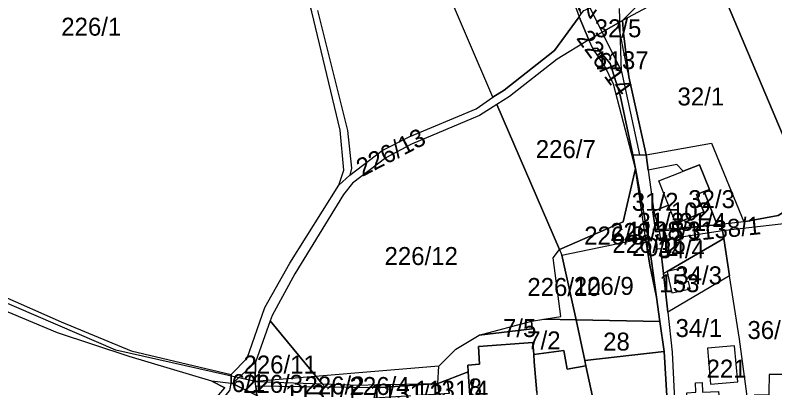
# Model space of a CAD drawing. Extents: x -623250 to -619626, y -1079612 to -1075424.
# Drawn here: x -622012.8 to -621589.3, y -1077337.8 to -1077130.2 of the extents above; entities that cross this region are included whole.
import ezdxf

# ---------------------------------------------------------------- set-up
doc = ezdxf.new("R2010")
doc.units = 0
for name, color, linetype in [('Cestní síť', 7, 'Continuous'), ('Hranice převzatá (k_ú_Džbánov - vnitřní obvod)', 7, 'Continuous'), ('Hranice šetřená (k_ú_Džbánov - vnitřní obvod)', 7, 'Continuous'), ('Parcela nároku', 7, 'Continuous'), ('Parcelní číslo', 7, 'Continuous')]:
    doc.layers.add(name, color=color, linetype=linetype)

msp = doc.modelspace()

# ---------------------------------------------------------------- linework, layer by layer
at = {"layer": 'Cestní síť'}
for p, q in [((-621700.59, -1077109.27), (-621674.74, -1077161.53)), ((-621674.74, -1077161.53), (-621675.8, -1077126.45)), ((-621674.74, -1077161.53), (-621664.7, -1077208.02)), ((-621956.73, -1077316.77), (-622052.88, -1077275.46)), ((-621878.96, -1077334.38), (-621956.73, -1077316.77)), ((-621776.53, -1077325.85), (-621878.96, -1077334.38))]:
    msp.add_line(p, q, dxfattribs=at)
at = {"layer": 'Hranice převzatá (k_ú_Džbánov - vnitřní obvod)'}
msp.add_lwpolyline([(-621820.79, -1077336.29), (-621811.3, -1077336.07), (-621804.95, -1077335.91), (-621777.05, -1077335.46)], dxfattribs=at)
at = {"layer": 'Hranice šetřená (k_ú_Džbánov - vnitřní obvod)'}
for points in [[(-621777.05, -1077335.46), (-621776.53, -1077325.85), (-621767.08, -1077316.28), (-621754.15, -1077308.49), (-621724.62, -1077305.04), (-621725.01, -1077300.64), (-621718.03, -1077299.58), (-621700.04, -1077299.94), (-621707.97, -1077263.85), (-621661.46, -1077254.24), (-621666.99, -1077215.55), (-621668.35, -1077208.09), (-621661.04, -1077207.94), (-621670.74, -1077164.6), (-621673.7, -1077140.26), (-621674.17, -1077133.23), (-621658.06, -1077117.09)], [(-621979.33, -1077434.11), (-621981.48, -1077418.71), (-621967.44, -1077419.71), (-621940.51, -1077416.47), (-621930.63, -1077410.65), (-621923.08, -1077402.05), (-621922.91, -1077399.82), (-621921.11, -1077391), (-621919.24, -1077381.82), (-621913.99, -1077368.92), (-621903.63, -1077352.03), (-621893.06, -1077339.39), (-621892.26, -1077335.34), (-621891.68, -1077335.41), (-621878.09, -1077342.07), (-621878.67, -1077336.93), (-621878.96, -1077334.38), (-621841.71, -1077335.6), (-621820.79, -1077336.29)]]:
    msp.add_lwpolyline(points, dxfattribs=at)
at = {"layer": 'Parcela nároku'}
for points in [[(-621862.28, -1077073.68), (-621884.15, -1076991.03), (-621993.08, -1077002.63), (-622102.16, -1077014.18), (-622094.75, -1077078.52), (-622077.89, -1077147.06), (-622076.74, -1077150.89), (-622049.49, -1077211.69), (-622030.93, -1077247.2), (-622020.83, -1077286.22), (-621987.11, -1077301.08), (-621948.12, -1077317.22), (-621892.3, -1077330.5), (-621883.37, -1077321.39), (-621873.67, -1077293.17), (-621859.64, -1077268.41), (-621832.26, -1077224.99), (-621829.56, -1077216.51), (-621831.64, -1077194.31), (-621847.29, -1077128.33)], [(-621742.89, -1077027.94), (-621730.03, -1077051.19), (-621717.08, -1077079.76), (-621698.44, -1077131.08), (-621712.03, -1077149.92), (-621740.17, -1077171.93), (-621746.44, -1077175.87), (-621802.34, -1077045.59)], [(-621737.82, -1077026.43), (-621742.89, -1077027.94), (-621730.03, -1077051.19), (-621717.08, -1077079.76), (-621698.44, -1077131.08), (-621697.15, -1077129.38), (-621704.43, -1077111.1), (-621716.26, -1077072.94), (-621722.92, -1077054.35), (-621730.97, -1077036.31)], [(-621523.17, -1077195.12), (-621571.7, -1077066.1), (-621579.59, -1077070.93), (-621623.27, -1077105.92), (-621571.51, -1077228.57), (-621549.32, -1077220.52), (-621537.72, -1077208.73)], [(-621570.38, -1077230.98), (-621571.51, -1077228.57), (-621623.27, -1077105.92), (-621674.17, -1077133.23), (-621673.7, -1077140.26), (-621670.74, -1077164.6), (-621661.04, -1077207.94), (-621624.64, -1077201.52), (-621606.64, -1077245.37), (-621587.33, -1077241.87)], [(-621892.3, -1077330.5), (-621883.37, -1077321.39), (-621873.67, -1077293.17), (-621859.64, -1077268.41), (-621832.26, -1077224.99), (-621826.2, -1077219.39), (-621808.22, -1077205.68), (-621793.14, -1077198.02), (-621755.81, -1077182.33), (-621746.44, -1077175.87), (-621740.17, -1077171.93), (-621712.03, -1077149.92), (-621698.44, -1077131.08), (-621692.89, -1077143.94), (-621710.61, -1077154.71), (-621737.17, -1077175.56), (-621744.25, -1077179.97), (-621753.86, -1077186.11), (-621791.79, -1077202.14), (-621806.2, -1077209.69), (-621824.78, -1077223.79), (-621829.76, -1077230.05), (-621856.84, -1077274.4), (-621869.44, -1077297.51), (-621870.52, -1077300.51), (-621878.78, -1077323.55), (-621891.68, -1077335.41), (-621892.26, -1077335.34)], [(-621674.17, -1077133.23), (-621676.84, -1077134.66), (-621671.56, -1077160.93), (-621670.74, -1077164.6), (-621673.7, -1077140.26)], [(-621710.61, -1077154.71), (-621737.17, -1077175.56), (-621744.25, -1077179.97), (-621709.31, -1077260.78), (-621673.9, -1077245.39), (-621666.99, -1077215.55), (-621679.28, -1077168.63), (-621684, -1077158.71), (-621690.78, -1077148.84), (-621692.89, -1077143.94)], [(-621688.26, -1077148.59), (-621681.03, -1077157.16), (-621675.57, -1077174.81), (-621668.35, -1077208.09), (-621666.99, -1077215.55), (-621679.28, -1077168.63), (-621684, -1077158.71), (-621690.78, -1077148.84)], [(-621824.78, -1077223.79), (-621829.76, -1077230.05), (-621856.84, -1077274.4), (-621869.44, -1077297.51), (-621870.52, -1077300.51), (-621841.71, -1077335.6), (-621820.79, -1077336.29), (-621811.3, -1077336.07), (-621804.95, -1077335.91), (-621777.05, -1077335.46), (-621776.53, -1077325.85), (-621767.08, -1077316.28), (-621754.15, -1077308.49), (-621725.01, -1077300.64), (-621718.03, -1077299.58), (-621708.56, -1077298.04), (-621712.89, -1077265.35), (-621709.31, -1077260.78), (-621744.25, -1077179.97), (-621753.86, -1077186.11), (-621791.79, -1077202.14), (-621806.2, -1077209.69)], [(-621624.64, -1077201.52), (-621606.64, -1077245.37), (-621621.37, -1077247.04), (-621628.74, -1077228.46), (-621625.75, -1077227.25), (-621631.33, -1077213.68), (-621640.41, -1077217.21), (-621643.96, -1077213.36), (-621659.81, -1077216.54), (-621661.04, -1077207.94)], [(-621661.46, -1077254.24), (-621666.99, -1077215.55), (-621673.9, -1077245.39), (-621709.31, -1077260.78), (-621707.97, -1077263.85)], [(-621666.99, -1077215.55), (-621659.97, -1077253.93), (-621661.46, -1077254.24)], [(-621648.61, -1077236.1), (-621651.16, -1077229.5), (-621653.9, -1077222.45), (-621642.07, -1077217.85), (-621640.41, -1077217.21), (-621643.96, -1077213.36), (-621659.81, -1077216.54), (-621656.73, -1077239.48)], [(-621653.9, -1077222.45), (-621642.07, -1077217.85), (-621640.41, -1077217.21), (-621631.33, -1077213.68), (-621625.75, -1077227.25), (-621628.74, -1077228.46), (-621632.86, -1077230.12), (-621628.82, -1077239.77), (-621644.33, -1077246.24), (-621648.48, -1077236.42), (-621648.61, -1077236.1), (-621651.16, -1077229.5)], [(-621632.86, -1077230.12), (-621628.74, -1077228.46), (-621621.37, -1077247.04), (-621643.19, -1077248.8), (-621644.33, -1077246.24), (-621628.82, -1077239.77)], [(-621606.64, -1077245.37), (-621621.37, -1077247.04), (-621642.79, -1077249.7), (-621653.8, -1077250.72), (-621653.03, -1077255.07), (-621648.68, -1077254.77), (-621618.44, -1077250.2), (-621584.31, -1077246.2), (-621576.81, -1077248.47), (-621567.88, -1077234.07), (-621570.38, -1077230.98), (-621587.33, -1077241.87)], [(-621648.48, -1077236.42), (-621648.61, -1077236.1), (-621656.73, -1077239.48), (-621654, -1077249.58), (-621643.19, -1077248.8), (-621644.33, -1077246.24)], [(-621654, -1077249.58), (-621643.19, -1077248.8), (-621621.37, -1077247.04), (-621642.79, -1077249.7), (-621653.8, -1077250.72), (-621655.62, -1077250.89), (-621657.3, -1077239.86), (-621656.73, -1077239.48)], [(-622110.98, -1077248.42), (-622120.1, -1077242.65), (-622141.17, -1077304.62), (-622091.65, -1077325.32), (-622091.8, -1077327.95), (-622142.04, -1077307.19), (-622173.19, -1077398.85), (-622025.85, -1077415.55), (-621981.48, -1077418.71), (-621940.98, -1077412.64), (-621934.21, -1077407.78), (-621917.8, -1077369.23), (-621906.89, -1077350.6), (-621895.93, -1077337.87), (-621903.13, -1077334.05), (-621949.28, -1077320.36), (-621989.19, -1077307.24), (-622022.59, -1077293.19)], [(-621600.79, -1077341.91), (-621599.98, -1077368.66), (-621601.14, -1077368.85), (-621608.91, -1077310.81), (-621614.46, -1077275.5), (-621617.74, -1077254.62), (-621618.44, -1077250.2), (-621584.31, -1077246.2), (-621576.81, -1077248.47), (-621571.17, -1077298.59), (-621567.58, -1077330.5), (-621592.44, -1077330.4), (-621592.59, -1077340.5), (-621592.59, -1077341.84)], [(-621652.41, -1077264.49), (-621647.96, -1077264.19), (-621648.68, -1077254.77), (-621618.44, -1077250.2), (-621617.74, -1077254.62), (-621649.34, -1077272.95), (-621651.28, -1077274.14)], [(-621655.23, -1077287.36), (-621653.31, -1077300.87), (-621700.04, -1077299.94), (-621707.97, -1077263.85), (-621661.46, -1077254.24), (-621658.93, -1077269.47)], [(-621661.46, -1077254.24), (-621659.97, -1077253.93), (-621655.23, -1077287.36), (-621658.93, -1077269.47)], [(-621647.96, -1077264.19), (-621648.68, -1077254.77), (-621653.03, -1077255.07), (-621655.42, -1077255.25), (-621655.02, -1077260.36), (-621652.78, -1077260.24), (-621652.41, -1077264.49)], [(-621649.34, -1077272.95), (-621617.74, -1077254.62), (-621614.46, -1077275.5), (-621648.95, -1077295.76), (-621651.28, -1077274.14)], [(-621718.03, -1077299.58), (-621708.56, -1077298.04), (-621712.89, -1077265.35), (-621709.31, -1077260.78), (-621707.97, -1077263.85), (-621700.04, -1077299.94)], [(-621636.45, -1077282.76), (-621637.37, -1077278.62), (-621638.4, -1077278.85), (-621640.16, -1077270.98), (-621649.34, -1077272.95), (-621648.15, -1077278.49), (-621646.76, -1077284.97), (-621645.66, -1077284.73)], [(-621649.34, -1077272.95), (-621648.15, -1077278.49), (-621646.76, -1077284.97), (-621645.66, -1077284.73), (-621636.45, -1077282.76), (-621637.37, -1077278.62), (-621638.4, -1077278.85), (-621640.16, -1077270.98)], [(-621633.38, -1077340.29), (-621633.58, -1077335.08), (-621629.83, -1077334.92), (-621629.57, -1077340.18), (-621620.76, -1077339.89), (-621620.36, -1077343.9), (-621613.65, -1077343.5), (-621613.36, -1077347.44), (-621612.06, -1077360.48), (-621610.38, -1077370.32), (-621601.14, -1077368.85), (-621608.91, -1077310.81), (-621614.46, -1077275.5), (-621648.95, -1077295.76), (-621646.56, -1077318.01), (-621644.24, -1077363.61), (-621642.81, -1077363.8), (-621641.11, -1077345.45), (-621638.39, -1077345.5), (-621638.26, -1077340.7)], [(-621841.71, -1077335.6), (-621870.52, -1077300.51), (-621878.78, -1077323.55), (-621878.96, -1077334.38)], [(-621777.05, -1077335.46), (-621776.53, -1077325.85), (-621767.08, -1077316.28), (-621754.15, -1077308.49), (-621724.62, -1077305.04), (-621725.01, -1077300.64), (-621718.03, -1077299.58), (-621700.04, -1077299.94), (-621695.25, -1077322.6), (-621694.61, -1077325.64), (-621705.03, -1077327.44), (-621706.89, -1077317.07), (-621723.69, -1077319.3), (-621724.25, -1077312.55), (-621754.48, -1077314.8), (-621753.9, -1077324.68), (-621760.48, -1077325.2), (-621760.22, -1077329.01), (-621771.66, -1077333.4)], [(-621725.01, -1077300.64), (-621724.62, -1077305.04), (-621754.15, -1077308.49)], [(-621653.31, -1077300.87), (-621650.98, -1077317.62), (-621695.25, -1077322.6), (-621700.04, -1077299.94)], [(-621722.01, -1077340.46), (-621721.53, -1077346.44), (-621750.48, -1077349.15), (-621750.65, -1077346.65), (-621758.96, -1077347.22), (-621760.22, -1077329.01), (-621760.48, -1077325.2), (-621753.9, -1077324.68), (-621754.48, -1077314.8), (-621724.25, -1077312.55), (-621723.69, -1077319.3), (-621723.35, -1077323.39)], [(-621663.9, -1077358.78), (-621663.52, -1077360.47), (-621672.18, -1077363.66), (-621672.87, -1077361.1), (-621682.78, -1077363.66), (-621678.9, -1077377.73), (-621682.67, -1077378.82), (-621681.21, -1077384.14), (-621684.1, -1077385), (-621686.57, -1077362.36), (-621694.61, -1077325.64), (-621695.25, -1077322.6), (-621650.98, -1077317.62), (-621649.48, -1077342.22), (-621650.68, -1077342.3), (-621650.3, -1077348.41), (-621649.11, -1077348.34), (-621647.49, -1077374.81), (-621647.15, -1077380.39), (-621654.46, -1077382.4), (-621655.67, -1077377.74), (-621650.61, -1077376.43), (-621656.16, -1077355.19), (-621664.28, -1077357.31)], [(-621625.06, -1077335.81), (-621609.92, -1077334.48), (-621611.73, -1077314.46), (-621626.88, -1077315.81)], [(-621611.73, -1077314.46), (-621626.88, -1077315.81), (-621625.06, -1077335.81), (-621609.92, -1077334.48)], [(-621878.09, -1077342.07), (-621878.67, -1077336.93), (-621878.96, -1077334.38), (-621878.78, -1077323.55), (-621891.68, -1077335.41)], [(-621592.59, -1077340.5), (-621592.59, -1077341.84), (-621600.79, -1077341.91), (-621599.98, -1077368.66), (-621599.89, -1077370.95), (-621592.24, -1077371.02), (-621590.5, -1077370.88), (-621582.71, -1077370.17), (-621574.55, -1077369.43), (-621573.15, -1077359.17), (-621567.25, -1077359.56), (-621565.82, -1077343), (-621566.45, -1077340.93), (-621566.7, -1077339.72), (-621567.58, -1077330.5), (-621592.44, -1077330.4)], [(-621841.71, -1077335.6), (-621840.01, -1077337.41), (-621878.67, -1077336.93), (-621878.96, -1077334.38)], [(-621777.05, -1077335.46), (-621771.66, -1077333.4), (-621770.78, -1077341.04), (-621776.36, -1077341.42)], [(-621633.58, -1077335.08), (-621629.83, -1077334.92), (-621629.57, -1077340.18), (-621620.76, -1077339.89), (-621620.36, -1077343.9), (-621613.65, -1077343.5), (-621613.36, -1077347.44), (-621612.06, -1077360.48), (-621610.38, -1077370.32), (-621616.18, -1077371.29), (-621632.17, -1077373.96), (-621633.01, -1077374.1), (-621634.82, -1077364.54), (-621642.81, -1077363.8), (-621641.11, -1077345.45), (-621638.39, -1077345.5), (-621638.26, -1077340.7), (-621633.38, -1077340.29)], [(-621840.01, -1077337.41), (-621878.67, -1077336.93), (-621878.09, -1077342.07), (-621877.06, -1077342.65), (-621848.66, -1077343.39), (-621824.17, -1077344.4), (-621812.59, -1077343.68), (-621811.59, -1077337.77)], [(-621841.71, -1077335.6), (-621820.79, -1077336.29), (-621811.3, -1077336.07), (-621811.59, -1077337.77), (-621840.01, -1077337.41)], [(-621777.05, -1077335.46), (-621776.36, -1077341.42), (-621812.59, -1077343.68), (-621811.59, -1077337.77)], [(-621811.3, -1077336.07), (-621804.95, -1077335.91), (-621777.05, -1077335.46), (-621811.59, -1077337.77)]]:
    msp.add_lwpolyline(points, close=True, dxfattribs=at)
for points in [[(-621844.23, -1077127.58), (-621827.5, -1077194.48), (-621825.32, -1077215.49), (-621826.2, -1077219.39), (-621808.22, -1077205.68), (-621793.14, -1077198.02), (-621755.81, -1077182.33), (-621746.44, -1077175.87), (-621802.34, -1077045.59)], [(-621579.59, -1077070.93), (-621623.27, -1077105.92), (-621674.17, -1077133.23), (-621676.84, -1077134.66), (-621692.89, -1077143.94), (-621698.44, -1077131.08), (-621697.15, -1077129.38), (-621695.81, -1077127.62), (-621693.84, -1077126.83), (-621680.53, -1077120.3), (-621665.11, -1077112.7), (-621662.05, -1077111.23), (-621659.97, -1077110.21), (-621659.28, -1077112.27), (-621658.06, -1077117.09), (-621634.95, -1077102.27), (-621618.73, -1077093.83), (-621590.54, -1077071.06), (-621559.55, -1077050.01)], [(-621844.23, -1077127.58), (-621827.5, -1077194.48), (-621825.32, -1077215.49), (-621826.2, -1077219.39), (-621832.26, -1077224.99), (-621829.56, -1077216.51), (-621831.64, -1077194.31), (-621847.29, -1077128.33)], [(-621649.48, -1077342.22), (-621650.98, -1077317.62), (-621653.31, -1077300.87), (-621655.23, -1077287.36), (-621659.97, -1077253.93), (-621666.99, -1077215.55), (-621668.35, -1077208.09), (-621675.57, -1077174.81), (-621681.03, -1077157.16), (-621688.26, -1077148.59), (-621690.78, -1077148.84), (-621692.89, -1077143.94), (-621676.84, -1077134.66), (-621671.56, -1077160.93), (-621670.74, -1077164.6), (-621661.04, -1077207.94), (-621659.81, -1077216.54), (-621656.73, -1077239.48), (-621657.3, -1077239.86), (-621655.62, -1077250.89), (-621653.8, -1077250.72), (-621653.03, -1077255.07), (-621655.42, -1077255.25), (-621655.02, -1077260.36), (-621652.78, -1077260.24), (-621652.41, -1077264.49), (-621651.28, -1077274.14), (-621648.95, -1077295.76), (-621646.56, -1077318.01), (-621644.24, -1077363.61)], [(-622020.83, -1077286.22), (-621987.11, -1077301.08), (-621948.12, -1077317.22), (-621892.3, -1077330.5), (-621892.26, -1077335.34), (-621903.13, -1077334.05), (-621949.28, -1077320.36), (-621989.19, -1077307.24), (-622022.59, -1077293.19)], [(-621722.01, -1077340.46), (-621723.35, -1077323.39), (-621723.69, -1077319.3), (-621706.89, -1077317.07), (-621705.03, -1077327.44), (-621694.61, -1077325.64), (-621686.57, -1077362.36)], [(-621770.78, -1077341.04), (-621771.66, -1077333.4), (-621760.22, -1077329.01), (-621758.96, -1077347.22)], [(-621878.09, -1077342.07), (-621891.68, -1077335.41), (-621892.26, -1077335.34), (-621903.13, -1077334.05), (-621895.93, -1077337.87)]]:
    msp.add_lwpolyline(points, dxfattribs=at)

# ---------------------------------------------------------------- texts
at = {"layer": 'Parcelní číslo'}
for s, rotation, p in [('254/4', 55.5481, (-621692.21, -1077133.05)), ('226/14', 306.2084, (-621700.28, -1077143.09)), ('226/13', 27.3961, (-621819.25, -1077220.4)), ('1138/1', 5.801, (-621637.39, -1077256.3))]:
    msp.add_text(s, height=10, rotation=rotation, dxfattribs=at).set_placement(p)
for s, p in [('226/1', (-621987.07, -1077141.63)), ('32/5', (-621689.7, -1077142.53)), ('1137', (-621689.38, -1077160.32)), ('32/1', (-621643.52, -1077180.53)), ('226/7', (-621722.56, -1077209.82)), ('31/2', (-621668.99, -1077239.21)), ('32/3', (-621637.54, -1077237.7)), ('102', (-621647.22, -1077244.54)), ('31/3', (-621665.86, -1077250.32)), ('31/4', (-621642.43, -1077250.41)), ('226/15', (-621681.11, -1077256.01)), ('1138/3', (-621671.47, -1077255.19)), ('226/8', (-621695.54, -1077258)), ('226/16', (-621679.85, -1077262.63)), ('20/2', (-621668.9, -1077264.42)), ('226/12', (-621806.85, -1077269.41)), ('34/4', (-621654.32, -1077265.61)), ('34/3', (-621644.77, -1077280.16)), ('226/9', (-621701.38, -1077286.05)), ('153', (-621653.67, -1077284.54)), ('226/10', (-621727.24, -1077286.65)), ('7/5', (-621740.82, -1077309.56)), ('34/1', (-621644.62, -1077309.52)), ('36/1', (-621604.53, -1077310.62)), ('7/2', (-621727.29, -1077316.41)), ('28', (-621684.99, -1077317.07)), ('226/11', (-621885.49, -1077329.86)), ('221', (-621627.31, -1077332.13)), ('6/1', (-621892.05, -1077340.19)), ('226/3', (-621885.73, -1077340.63)), ('226/2', (-621851.48, -1077341.49)), ('226/4', (-621826.33, -1077341.82)), ('1131/3', (-621815.14, -1077345.82)), ('1131/4', (-621789.93, -1077343.9)), ('8', (-621759.98, -1077342.6)), ('1131/1', (-621862.27, -1077346.06))]:
    msp.add_text(s, height=10, dxfattribs=at).set_placement(p)

doc.saveas('drawing.dxf')
